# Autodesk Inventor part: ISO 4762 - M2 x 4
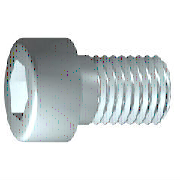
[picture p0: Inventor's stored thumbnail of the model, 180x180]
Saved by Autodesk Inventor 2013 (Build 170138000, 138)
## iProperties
IsCustomPart: 0
Created: 2012-02
Part Number: ISO 4762 - M2 x 4
Material: Stainless Steel, 440C
Description: Hexagon Socket Head Cap Screw
Document SubType Name: Modeling
Standard: ISO 4762
Designer: rYan
Standard Revision: Fourth edition 2004-03-01
Standards Organization: ISO
Language: en-US
Size Designation: M2 x 4
Categories: <MemberInstance><Categories><Category DisplayName="Fasteners" InternalName="e4da775c-781d-43d5-af7c-5136215cf5a6" Mnemonic="FSTN"><Category DisplayName="Bolts"
Density: 7.75 g/cm^3
Author: rYan
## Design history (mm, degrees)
sketch "Sketch1"
  geometry: L1 (-0.5, 0)-(4, 0); L2 (4, 0)-(4, 1); L3 (4, 1)-(1, 1); L4 (1, 1)-(0.755, 1); L5 (0.755, 1)-(0, 1); L6 (0, 1)-(0, 1.9); L7 (0, 1.9)-(-2, 1.9); L8 (-2, 1.9)-(-2, 0.866); L9 (-2, 0.866)-(-1, 0.866); L10 (-1, 0.866)-(-0.5, 0); L11 (-3.2, 0)-(5.2, 0) reference; L12 (0, -0.38)-(0, 2.28) reference; L13 (1, 1)-(0, 1)
  constraints: 22 end point, 6 parallel, 2 collinear, 2 perpendicular, 1 horizontal, 1 point on line
  dimensions: "d1" = 3 distance from line of L3.end L2 (= GEL); "d2" = 0.24548 distance of L4.end L3.end (computed from GAL); "d3" = 2 distance between parallel lines of L8 L6 (= KOH); "d4" = 1 distance of L8.end L9.end (= INTI); "d5" = 60 deg angle of L10 L1; "d6" = 2 diameter of L3 L1 (= GD); "d7" = 2 diameter of L5 L1 (= BDM); "d8" = 1.73205 diameter of L9 L1 (= 1.1547 x SW); "d9" = 3.8 diameter of L7 L1 (= KOD); "d26" = 4 distance between parallel lines of L12 L2 (= NLG)
revolve "Body" sketch "Sketch1" stored, may be unused: angle "d10" = 90 deg
sketch "Sketch2"
  geometry: L1 (0, -2.66)-(0, 2.66) reference; L2 (-2.66, 0)-(2.66, 0) reference; L3 (0.866, 0)-(0.433, -0.75); L4 (0.433, -0.75)-(-0.433, -0.75); L5 (-0.433, -0.75)-(-0.866, 0); L6 (-0.866, 0)-(-0.433, 0.75); L7 (-0.433, 0.75)-(0.433, 0.75); L8 (0.433, 0.75)-(0.866, 0); 2 further points
  constraints: 12 end point, 1 coincident, 1 horizontal alignment, 1 point on line, 12 other
extrude "Slot" join sketch "Sketch2" stored distance "d11" = 10; taper "d12" = 0 deg
workplane "Work Plane1"
fillet "Fillet2" dims "d30" = 0.1 (= R)
body "Solid1"
fillet "Fillet1" dims "d17" = 0.2 (= RR)
feature "Thread" dims "d13" = 3 (= GEL), "d14" = 0
chamfer "Chamfer1" distance "d15" = 0.24538 (= -0.5 x SPD + 0.5 x GD); stored, may be unused: second distance "d16" = 0.24538 (= GUL), angle "d27" = 45 deg
other parameters: "GD" = 2 [user parameter; used in 2 equation terms], "NLG" = 4 [user parameter; used in 1 equation term], "GEL" = 3 [user parameter; used in 2 equation terms], "KOD" = 3.8 [user parameter; used in 1 equation term], "KOH" = 2 [user parameter; used in 1 equation term], "INTI" = 1 [user parameter; used in 1 equation term], "GAL" = 0.24538 (= 0.61345 x PTC) [user parameter; used in 1 equation term], "GUL" = 0.24538 (= 0.61345 x PTC) [user parameter; used in 1 equation term], "BDM" = 2 (= NND) [user parameter; used in 1 equation term], "SW" = 1.5 [user parameter; used in 2 equation terms], "RR" = 0.2 [user parameter; used in 1 equation term], "SPD" = 1.50924 (= NND - 1.2269 x PTC) [user parameter; used in 1 equation term], "d19" = 0, "d28" = 0, "d29" = 0, "R" = 0.1 [user parameter; used in 1 equation term], "TOA" = 30 deg [user parameter], "GD1" = 1.50924 (= THREADDIA - 1.2269 x PTC) [user parameter], "THREADDIA" = 2 [user parameter; used in 1 equation term], "FAWI" = 45 deg [user parameter], "TPU" = 25 (computed from PTC) [user parameter], "PTC" = 0.4 [user parameter; used in 5 equation terms], "NND" = 2 [user parameter; used in 2 equation terms], "E0" = 1.7325 (= 1.155 x SW) [user parameter]
